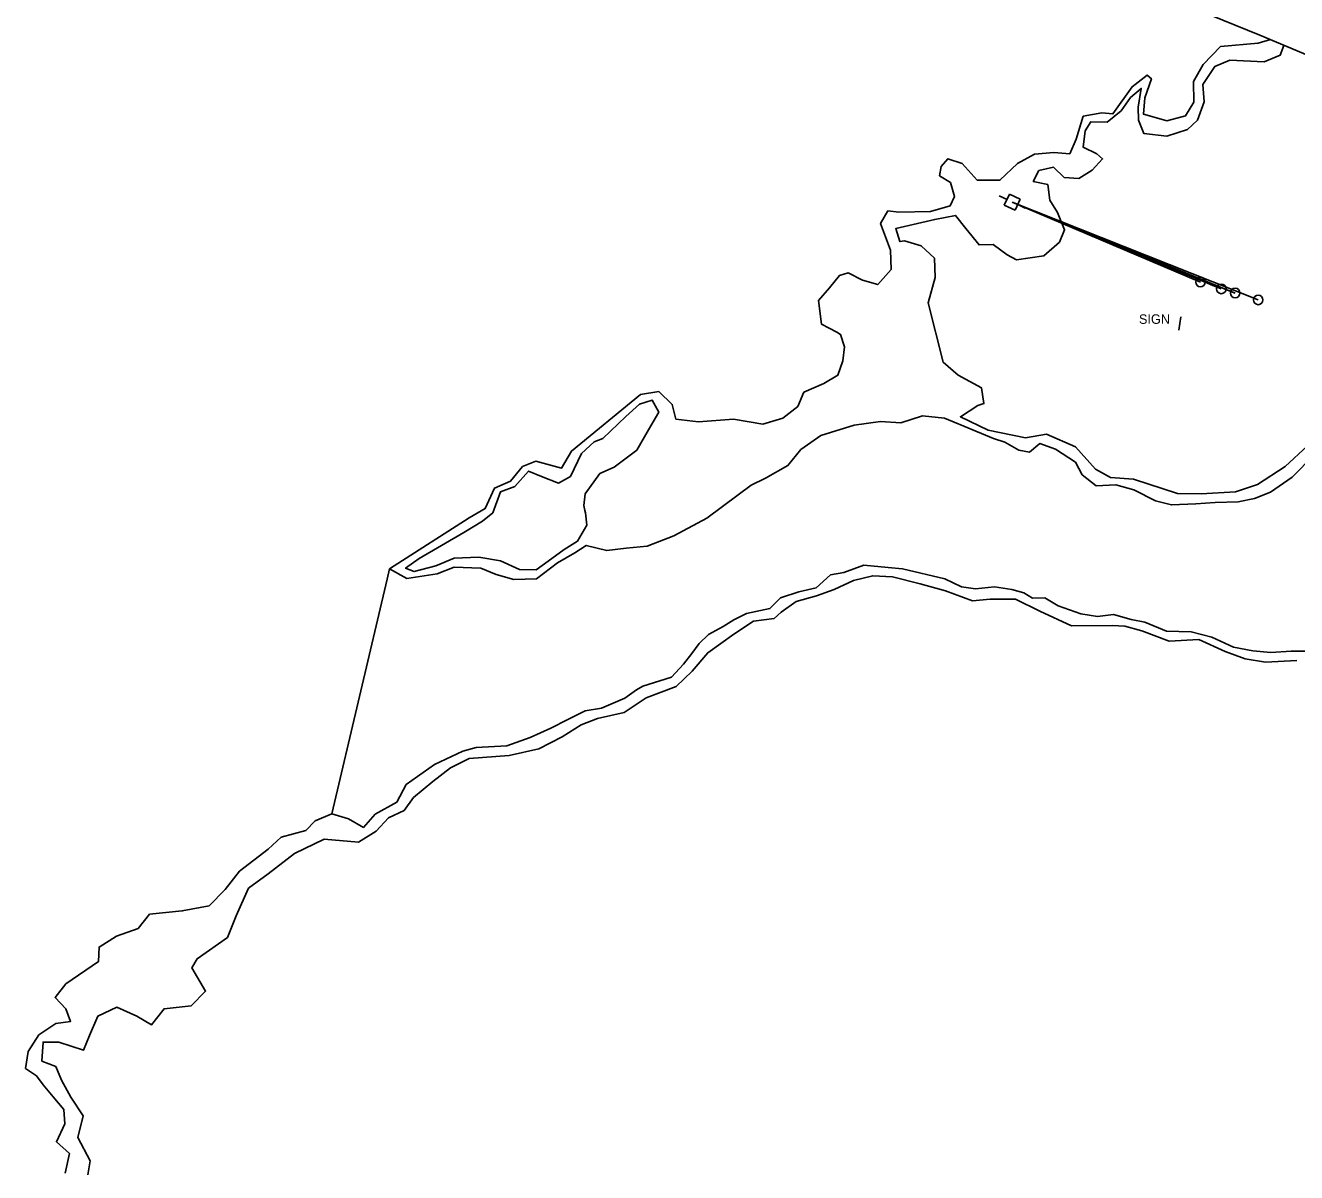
# Model space of a CAD drawing. Extents: x 2160437 to 2172832, y 205694 to 212444.
# Drawn here: x 2169223 to 2169759, y 207334 to 207818 of the extents above; entities that cross this region are included whole.
import ezdxf

# ---------------------------------------------------------------- set-up
doc = ezdxf.new("R2010")
doc.units = 0
for name, color, linetype in [('RD_EX_Bldg_Signs', 7, 'Continuous'), ('RD_EX_BldgApp_txCode', 7, 'Continuous'), ('RD_EX_Bridge', 7, 'Continuous'), ('RD_EX_H2O', 7, 'Continuous'), ('RD_EX_H2O_River', 7, 'Continuous'), ('RD_EX_UT', 7, 'Continuous'), ('RD_EX_UT_Guy', 7, 'Continuous'), ('RD_EX_VEG_ShrubLine', 7, 'Continuous')]:
    doc.layers.add(name, color=color, linetype=linetype)

# ---------------------------------------------------------------- blocks, each defined once
blk = doc.blocks.new('PP')
at = {"layer": 'RD_EX_UT'}
for p, q in [((2.49, 2.51), (-2.51, 2.51)), ((-2.51, 2.51), (-2.51, -2.49)), ((2.49, -2.49), (2.49, 2.51)), ((-5.94, -0.05), (-2.47, -0.05)), ((-2.51, -2.49), (2.49, -2.49)), ((2.42, -0.05), (6.06, -0.05))]:
    blk.add_line(p, q, dxfattribs=at)

msp = doc.modelspace()

# ---------------------------------------------------------------- linework, layer by layer
at = {"layer": 'RD_EX_Bldg_Signs'}
msp.add_lwpolyline([(2169709.74, 207689.37), (2169710.65, 207695.02)], dxfattribs=at)
at = {"layer": 'RD_EX_Bridge'}
msp.add_lwpolyline([(2169706.83, 207828.97), (2169743.97, 207813.84), (2169780.86, 207798.32)], dxfattribs=at)
at = {"layer": 'RD_EX_H2O'}
for points in [[(2169376.9, 207588.71), (2169384.2, 207584.71), (2169396.98, 207586.59), (2169404.06, 207589.37), (2169415.43, 207589.05), (2169421.82, 207586.32), (2169429.22, 207584.25), (2169438.83, 207584.53), (2169447.72, 207591.25), (2169454.95, 207595.47), (2169459.86, 207598.62), (2169468.51, 207596.39), (2169476.64, 207597.45), (2169485.56, 207598.24), (2169496.73, 207602.6), (2169510.65, 207610.07), (2169523.86, 207620), (2169529.4, 207624.08), (2169535.4, 207626.94), (2169544.87, 207632.27), (2169550.32, 207639.04), (2169558.74, 207644.96), (2169572.85, 207649.29), (2169583.94, 207650.82), (2169592.58, 207650.32), (2169601.61, 207653.21), (2169610.88, 207652.32), (2169619.11, 207648.95), (2169631.56, 207643.65), (2169636.46, 207642.12), (2169642.25, 207638.75), (2169646.79, 207637.99), (2169651.18, 207641.58), (2169657.73, 207639.19), (2169666.2, 207633.67), (2169669.07, 207628.38), (2169674.9, 207623.77), (2169683.25, 207624.16), (2169690.81, 207622.02), (2169700, 207617.4), (2169706.63, 207615.68), (2169716.96, 207616.13), (2169725.06, 207616.7), (2169734.79, 207617.02), (2169741.66, 207618.46), (2169748.47, 207621.04), (2169757.65, 207627.42), (2169766.87, 207636.85)], [(2169763.79, 207553.99), (2169757.24, 207553.93), (2169748.56, 207553.43), (2169741.03, 207554.13), (2169732.9, 207555.73), (2169723.68, 207559.83), (2169715.06, 207562.14), (2169704.6, 207562.45), (2169695.44, 207566.24), (2169689.64, 207567.37), (2169682.28, 207569.53), (2169675.52, 207568.56), (2169668.39, 207569.68), (2169658.86, 207573.1), (2169653.24, 207576.45), (2169648, 207576.31), (2169644.41, 207578.66), (2169639.35, 207580.03), (2169632.06, 207581.09), (2169624.05, 207580.28), (2169618.05, 207581.2), (2169611.02, 207584.53), (2169593.18, 207588.74), (2169587.24, 207589.32), (2169576.89, 207590.3), (2169568.54, 207587.2), (2169562.9, 207586.23), (2169556.78, 207580.67), (2169549.51, 207579.02), (2169541.71, 207576.55), (2169537.27, 207571.94), (2169527.44, 207569.83), (2169522.08, 207567.25), (2169517.65, 207564.35), (2169511.38, 207561.02), (2169507.4, 207557.24), (2169504.35, 207553.03), (2169500.86, 207548.52), (2169495.82, 207543.09), (2169483.73, 207539.16), (2169481, 207537.66), (2169476.11, 207534.1), (2169466.26, 207529.95), (2169459.42, 207528.81), (2169452.13, 207525.13), (2169444.96, 207521.49), (2169436.22, 207517.55), (2169426.35, 207514.03), (2169413.41, 207513.34), (2169407.82, 207511.83), (2169395.84, 207506.22), (2169383.92, 207497.73), (2169379.87, 207490.34), (2169370.84, 207485.21), (2169365.84, 207479.62), (2169359.54, 207483.32), (2169352.45, 207485.41)]]:
    msp.add_lwpolyline(points, dxfattribs=at)
at = {"layer": 'RD_EX_H2O_River'}
msp.add_lwpolyline([(2169240.08, 207333.82), (2169241.92, 207342.04), (2169236.37, 207347.03), (2169239.92, 207354.57), (2169239.47, 207360.69), (2169234.98, 207366.01), (2169230.71, 207371.12), (2169228.01, 207374.8), (2169223.27, 207378), (2169224.39, 207385.12), (2169228.92, 207392.11), (2169236.1, 207396.87), (2169242.32, 207397.79), (2169240.28, 207403.1), (2169235.77, 207407.92), (2169240.34, 207413.67), (2169254.03, 207423.08), (2169254.36, 207429.14), (2169261.71, 207433.82), (2169270.8, 207436.99), (2169275.61, 207443.03), (2169289.4, 207444.45), (2169300.77, 207446.57), (2169307.58, 207453.43), (2169313.58, 207461.17), (2169325.69, 207470.49), (2169331.16, 207475.52), (2169341.55, 207478.4), (2169345.52, 207482.39), (2169352.45, 207485.41), (2169375.85, 207584.4), (2169376.9, 207588.71), (2169410.41, 207610.22), (2169417.2, 207614.14), (2169421.13, 207622.72), (2169427.91, 207625.73), (2169432.97, 207631.86), (2169438.52, 207634.2), (2169449.36, 207631.17), (2169453.59, 207638.4), (2169482.66, 207662.25), (2169490.45, 207663.46), (2169496.14, 207658.1), (2169497.68, 207651.9), (2169507.21, 207650.68), (2169522, 207651.84), (2169534.38, 207649.73), (2169542.75, 207652.21), (2169549.13, 207657.23), (2169551.66, 207663.2), (2169559.99, 207666.92), (2169565.97, 207670.39), (2169568, 207676.39), (2169568.71, 207682.38), (2169567.04, 207687.63), (2169565.52, 207688.53), (2169559.11, 207691.88), (2169557.78, 207701.86), (2169562.37, 207707.19), (2169566.62, 207712.47), (2169570.28, 207713.55), (2169576.39, 207710.44), (2169582.79, 207708.63), (2169588.46, 207714.99), (2169588.1, 207723.1), (2169584, 207734.36), (2169587.05, 207739.68), (2169591.71, 207739.17), (2169605, 207739.5), (2169613.29, 207741.81), (2169615.1, 207745.76), (2169613.41, 207751.63), (2169608.84, 207754.54), (2169609.54, 207758.5), (2169612.33, 207761.7), (2169618.36, 207759.75), (2169624.69, 207752.67), (2169634.35, 207752.62), (2169641.78, 207759.71), (2169648.89, 207763.68), (2169657.03, 207764.33), (2169663.81, 207763.77), (2169666.54, 207769.95), (2169669.45, 207779.62), (2169677.32, 207781), (2169682.01, 207780.58), (2169690.04, 207792.08), (2169696.38, 207797.02), (2169698.21, 207795.46), (2169695.42, 207787.37), (2169694.82, 207780.51), (2169699.42, 207779.22), (2169704.73, 207777.7), (2169712.62, 207779.79), (2169716.16, 207785.5), (2169715.99, 207794.24), (2169720.1, 207801.42), (2169727.38, 207809.08), (2169743.2, 207810.48), (2169748.45, 207811.96)], dxfattribs=at)
at = {"layer": 'RD_EX_UT'}
for p, q in [((2169718.91, 207709.7), (2169714.32, 207711.68)), ((2169727.71, 207706.78), (2169723.1, 207708.71)), ((2169733.55, 207705.07), (2169728.9, 207706.9)), ((2169743.26, 207702.15), (2169738.6, 207703.95))]:
    msp.add_line(p, q, dxfattribs=at)
for centre in [(2169718.91, 207709.7), (2169727.71, 207706.78), (2169733.55, 207705.07), (2169743.26, 207702.15)]:
    msp.add_circle(centre, 2, dxfattribs=at)
at = {"layer": 'RD_EX_UT_Guy'}
for points in [[(2169743.26, 207702.15), (2169639.53, 207743.4)], [(2169733.55, 207705.07), (2169639.53, 207743.4)], [(2169727.71, 207706.78), (2169639.53, 207743.4)], [(2169718.91, 207709.7), (2169639.53, 207743.4)]]:
    msp.add_lwpolyline(points, dxfattribs=at)
at = {"layer": 'RD_EX_VEG_ShrubLine'}
for points in [[(2169764.11, 207640.67), (2169754.6, 207631.84), (2169742.92, 207624.26), (2169733.66, 207621.27), (2169719.25, 207620.29), (2169709.18, 207620.43), (2169690.62, 207626.5), (2169681.02, 207627.23), (2169674.65, 207630.77), (2169666.23, 207640.18), (2169654.01, 207645.55), (2169645.08, 207644.01), (2169629.32, 207647.18), (2169617.67, 207652.88), (2169625.01, 207657.66), (2169627.59, 207658.41), (2169626.5, 207665.13), (2169616.73, 207670.37), (2169610.43, 207675.86), (2169604.04, 207700.91), (2169606.95, 207711.62), (2169606.68, 207719.74), (2169601.05, 207725.02), (2169594.1, 207727.08), (2169592.11, 207726.73), (2169590.37, 207732.26), (2169595.92, 207733.49), (2169606.85, 207736.11), (2169615.52, 207737.79), (2169619.91, 207732.26), (2169625.55, 207725.34), (2169631.49, 207725.56), (2169637.41, 207721.16), (2169641.32, 207719.01), (2169652.8, 207720.82), (2169659.42, 207726.5), (2169661.57, 207731.73), (2169658.57, 207739.06), (2169655.31, 207744.17), (2169654.53, 207750.8), (2169648.37, 207752.15), (2169650.78, 207756.74), (2169656.87, 207758.13), (2169661.49, 207753.77), (2169667.57, 207753.37), (2169673.17, 207756.92), (2169677.61, 207761.6), (2169675.26, 207763.8), (2169669.43, 207766.63), (2169670.32, 207773.46), (2169672.74, 207777.29), (2169679.5, 207777.14), (2169685.42, 207781.86), (2169689.35, 207787.47), (2169693.94, 207791.37), (2169692.57, 207783.5), (2169692.75, 207778.01), (2169694.97, 207772.41), (2169704.77, 207771.23), (2169713.44, 207774.04), (2169717.68, 207778.01), (2169720.42, 207785.7), (2169719.86, 207793.06), (2169724.93, 207800.67), (2169731.28, 207803.31), (2169745.74, 207802.64), (2169752.57, 207805.41), (2169754.05, 207809.42), (2169754.11, 207809.58)], [(2169249.58, 207333.08), (2169250.54, 207338.95), (2169245.34, 207348.83), (2169247.66, 207358), (2169242.49, 207365.93), (2169238.5, 207373), (2169236.05, 207378.76), (2169230.25, 207381.12), (2169230.75, 207389.09), (2169237.38, 207389.1), (2169247.79, 207385.7), (2169250.3, 207391.84), (2169253.81, 207400.06), (2169261.81, 207403.83), (2169270.32, 207400.07), (2169276.48, 207396.38), (2169281.74, 207403.19), (2169293.21, 207404.45), (2169299.26, 207410.64), (2169293.43, 207420.35), (2169295.72, 207424.23), (2169308.49, 207433.2), (2169312.18, 207442.36), (2169317.32, 207454.01), (2169325.61, 207460.09), (2169336.74, 207468.58), (2169349.32, 207474.68), (2169349.32, 207474.68), (2169363.72, 207473.43), (2169371.23, 207478.03), (2169376.35, 207483.63), (2169383.01, 207486.84), (2169386.96, 207492.21), (2169395.12, 207499.01), (2169402.53, 207504.73), (2169410.46, 207508.69), (2169427.26, 207510), (2169439.78, 207512.76), (2169449.74, 207517.82), (2169457.71, 207522.97), (2169464.62, 207525.61), (2169475.87, 207528.14), (2169485.15, 207534.28), (2169497.82, 207539.12), (2169504.44, 207545.55), (2169511.05, 207553.32), (2169522.06, 207561.21), (2169530.31, 207566.64), (2169539.1, 207567.81), (2169542.03, 207570.44), (2169548.41, 207575), (2169556.99, 207577.38), (2169564.42, 207580.04), (2169572.5, 207583.77), (2169580.65, 207585.78), (2169589.06, 207585.34), (2169600.72, 207582.33), (2169611.34, 207579.5), (2169622.75, 207575.28), (2169630.17, 207575.91), (2169640.92, 207575.92), (2169651.16, 207570.81), (2169664.46, 207564.71), (2169681.61, 207564.89), (2169687.03, 207564.5), (2169694.16, 207562.6), (2169705.68, 207558.18), (2169718.23, 207558.89), (2169729.34, 207553.9), (2169737.72, 207550.72), (2169746.34, 207549.31), (2169759.51, 207550.05)]]:
    msp.add_lwpolyline(points, dxfattribs=at)
msp.add_lwpolyline([(2169459.5, 207612.38), (2169460.13, 207607.1), (2169456.13, 207600.38), (2169450.55, 207596.87), (2169443.76, 207591.94), (2169438.76, 207588.27), (2169431.71, 207588.45), (2169423.65, 207592.1), (2169414.51, 207593.69), (2169404.18, 207593.18), (2169396.4, 207589.98), (2169387.3, 207587.58), (2169383.61, 207588.97), (2169389.33, 207593.12), (2169408.23, 207604.01), (2169416.03, 207608.89), (2169420.42, 207612.37), (2169423.61, 207621.2), (2169429.69, 207623.46), (2169435.43, 207629.99), (2169441.02, 207627.63), (2169448.08, 207624.91), (2169453.24, 207627.73), (2169457.89, 207637.31), (2169463.15, 207642.34), (2169466.78, 207643.68), (2169476.57, 207652.94), (2169482.32, 207658.25), (2169487.67, 207659.92), (2169490.39, 207654.86), (2169486.04, 207647.38), (2169481.11, 207638.84), (2169471.65, 207631.66), (2169465.59, 207629), (2169459.36, 207620.29), (2169458.84, 207615.49), (2169459.28, 207613.35)], close=True, dxfattribs=at)

# ---------------------------------------------------------------- block references
at = {"layer": 'RD_EX_UT', "xscale": 1.0199999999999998, "yscale": 1.0199999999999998, "rotation": 154.862181}
msp.add_blockref('PP', (2169639.53, 207743.4), dxfattribs=at)

# ---------------------------------------------------------------- texts
at = {"layer": 'RD_EX_BldgApp_txCode'}
msp.add_text('SIGN', height=4, dxfattribs=at).set_placement((2169692.97, 207692.07))

doc.saveas('drawing.dxf')
